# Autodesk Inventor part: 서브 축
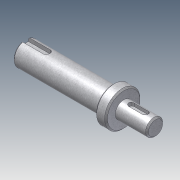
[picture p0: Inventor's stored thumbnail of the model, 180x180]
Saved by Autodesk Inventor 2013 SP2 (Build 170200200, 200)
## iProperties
Company: 한국ATC센터
Created: 2014-10
Part Number: 서브 축
Document SubType Name: Modeling
Designer: KYOUNG IL JANG
Density: 1 g/cm^3
Mass: 19.9624 g
Surface Area: 57.7178 cm^2
Volume: 19.9624 cm^3
Material: 일반
Author: KYOUNG IL JANG
Revision Number: 1
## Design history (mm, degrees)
sketch "스케치1"
  geometry: L1 (-16.331, 0)-(-108.831, 0); L2 (-16.331, 0)-(-16.331, -6); L3 (-16.331, -6)-(-38.831, -6); L4 (-38.831, -12.5)-(-46.5, -12.5); L5 (-46.5, -8.5)-(-108.831, -8.5); L6 (-108.831, -8.5)-(-108.831, 0); L7 (-46.5, -8.5)-(-46.5, -12.5); L8 (-38.831, -6)-(-38.831, -12.5); L9 (-46.5, 12.249)-(-46.5, -12.249) reference; L10 (-38.831, -17)-(-38.831, 17) reference; 2 further points
  constraints: 17 end point, 4 perpendicular, 2 collinear, 2 parallel, 1 horizontal, 1 midpoint, 1 point on line
  dimensions: "d1" = 12 diameter of L3 L1; "d2" = 25 diameter of L4 L1; "d3" = 17 diameter of L5 L1; "d4" = 62.33128 distance of L5.start L5.end (derived); "d18" = 22.5 distance of L2.end L3.end; "d20" = 70 distance between parallel lines of L6 L8
revolve "회전1" sketch "스케치1" stored, may be unused: angle "d5" = 90 deg
chamfer "모따기1" distance "d6" = 1; stored, may be unused: second distance "d7" = 2, angle "d8" = 45 deg
node "작업 평면1"
sketch "스케치2"
  geometry: L1 (11.25, 5)-(11.25, -5) reference; L2 (-5.75, -2)-(4.25, -2); L3 (4.25, 2)-(-5.75, 2); A1 r 2 centre (4.25, 0) between (4.25, -2) and (4.25, 2); A2 r 2 centre (-5.75, 0) between (-5.75, 2) and (-5.75, -2); 2 further points
  constraints: 4 end point, 4 point on circle, 4 tangent, 2 centre point, 1 horizontal alignment, 1 midpoint, 1 parallel, 1 perpendicular
  dimensions: "d9" = 4 distance between parallel lines of L2 L3; "d10" = 14 dimension on A1 A2; "d11" = 5 distance edge to line of A1 L1
extrude "돌출1" cut sketch "스케치2" distance "d12" = 2.5; taper "d13" = 0 deg
node "작업 평면2"
sketch "스케치3"
  geometry: L1 (-31.166, -7.5)-(-31.166, 7.5) reference; L2 (-31.166, 2.5)-(-15.666, 2.5); L3 (-15.666, -2.5)-(-31.166, -2.5); A1 r 2.5 centre (-15.666, 0) between (-15.666, -2.5) and (-15.666, 2.5); 2 further points
  constraints: 4 end point, 2 perpendicular, 2 point on circle, 2 point on line, 2 tangent, 1 centre point, 1 horizontal alignment, 1 midpoint
  dimensions: "d14" = 5 distance between parallel lines of L3 L2; "d15" = 18 dimension on A1 L1
extrude "돌출2" cut sketch "스케치3" distance "d16" = 3; taper "d17" = 0 deg
node "솔리드1"
node "참조4"
node "참조5"
